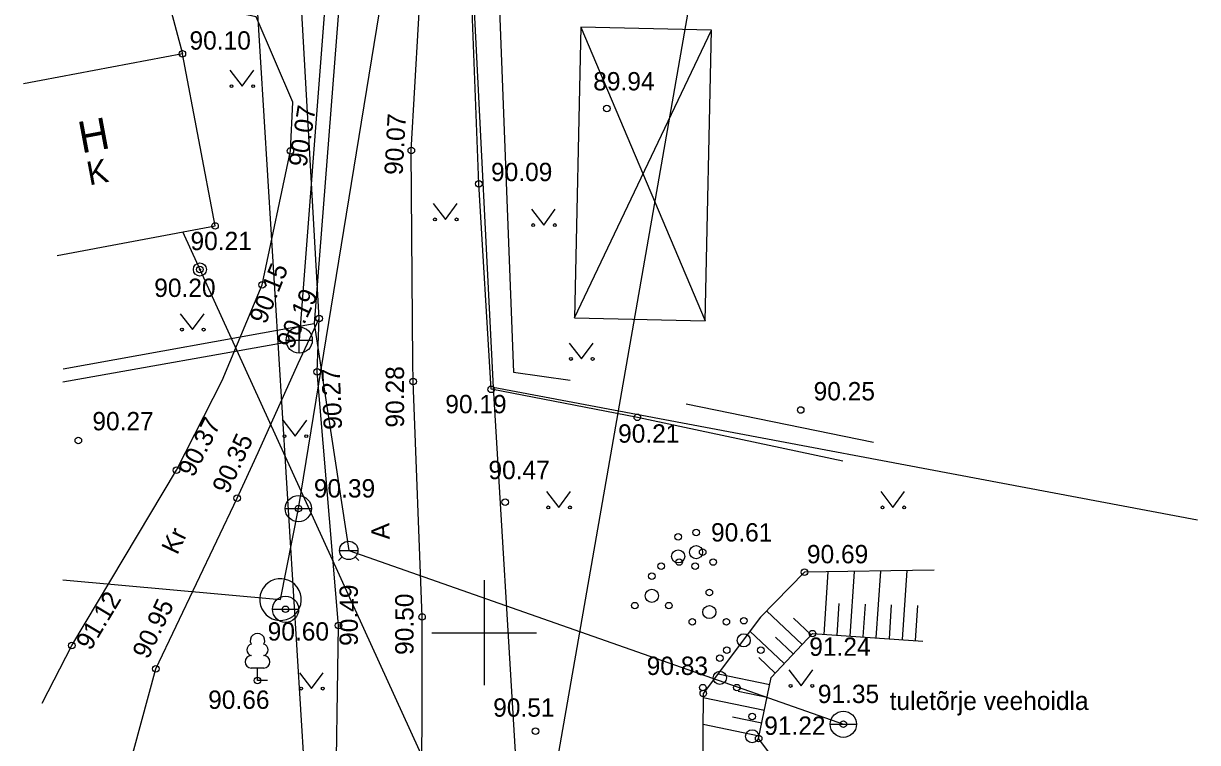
# Model space of a CAD drawing. Extents: x 648748 to 649126, y 6457789 to 6458252.
# Drawn here: x 648932.4 to 648977.24, y 6457945.81 to 6457973.26 of the extents above; entities that cross this region are included whole.
import ezdxf

# ---------------------------------------------------------------- set-up
doc = ezdxf.new("R2010")
doc.units = 0
for name, color, linetype in [('AED', 7, 'Continuous'), ('HALJASTUS', 7, 'Continuous'), ('HOONE', 7, 'Continuous'), ('KKAEV', 7, 'Continuous'), ('KORGUS-EH2000', 7, 'Continuous'), ('KTRASS', 7, 'Continuous'), ('MPOHULIIN', 7, 'Continuous'), ('PIIR', 7, 'Continuous'), ('POST', 7, 'Continuous'), ('PUU', 7, 'Continuous'), ('RAJATIS', 7, 'Continuous'), ('RAJATISEDET', 7, 'Continuous'), ('RELJEEF', 7, 'Continuous'), ('TEE', 7, 'Continuous'), ('VKAEV', 7, 'Continuous'), ('VORK', 7, 'Continuous'), ('VTRASS', 7, 'Continuous')]:
    doc.layers.add(name, color=color, linetype=linetype)

msp = doc.modelspace()

# ---------------------------------------------------------------- linework, layer by layer
at = {"layer": 'AED'}
msp.add_lwpolyline([(648963.692, 6457956.552), (648955.847, 6457958.221), (648950.262, 6457959.291), (648949.792, 6457967.138), (648949.494, 6457974.756), (648949.365, 6457978.667), (648950.63, 6457986.601)], dxfattribs=at)
at = {"layer": 'HALJASTUS'}
for p, q in [((648940.283, 6457971.47), (648940.746, 6457970.863)), ((648940.746, 6457970.863), (648941.192, 6457971.47)), ((648948.052, 6457966.384), (648948.515, 6457965.778)), ((648948.515, 6457965.778), (648948.961, 6457966.384)), ((648951.805, 6457966.17), (648952.269, 6457965.563)), ((648952.269, 6457965.563), (648952.714, 6457966.17)), ((648938.389, 6457962.176), (648938.853, 6457961.57)), ((648938.853, 6457961.57), (648939.298, 6457962.176)), ((648953.249, 6457961.058), (648953.712, 6457960.452)), ((648953.712, 6457960.452), (648954.158, 6457961.058)), ((648942.308, 6457958.108), (648942.772, 6457957.502)), ((648942.772, 6457957.502), (648943.217, 6457958.108)), ((648952.382, 6457955.391), (648952.845, 6457954.784)), ((648952.845, 6457954.784), (648953.291, 6457955.391)), ((648965.147, 6457955.391), (648965.611, 6457954.784)), ((648965.611, 6457954.784), (648966.056, 6457955.391)), ((648942.939, 6457948.473), (648943.403, 6457947.867)), ((648943.403, 6457947.867), (648943.848, 6457948.473)), ((648961.638, 6457948.576), (648962.101, 6457947.969)), ((648962.101, 6457947.969), (648962.547, 6457948.576))]:
    msp.add_line(p, q, dxfattribs=at)
msp.add_lwpolyline([(648951.554, 6457986.197), (648950.426, 6457977.749), (648951.117, 6457959.947)], dxfattribs=at)
for centre in [(648940.345, 6457970.863), (648941.174, 6457970.863), (648948.114, 6457965.778), (648948.943, 6457965.778), (648951.868, 6457965.563), (648952.697, 6457965.563), (648938.452, 6457961.57), (648939.281, 6457961.57), (648953.311, 6457960.452), (648954.14, 6457960.452), (648942.371, 6457957.502), (648943.2, 6457957.502), (648952.444, 6457954.784), (648953.273, 6457954.784), (648965.21, 6457954.784), (648966.039, 6457954.784), (648943.002, 6457947.867), (648943.831, 6457947.867), (648961.7, 6457947.969), (648962.529, 6457947.969)]:
    msp.add_circle(centre, 0.055, dxfattribs=at)
at = {"layer": 'HOONE'}
msp.add_lwpolyline([(648933.683, 6457964.404), (648939.716, 6457965.528), (648938.468, 6457972.096), (648932.399, 6457970.956)], dxfattribs=at)
at = {"layer": 'KKAEV'}
for p, q in [((648942.931, 6457960.671), (648942.931, 6457961.671)), ((648942.431, 6457961.171), (648943.431, 6457961.171))]:
    msp.add_line(p, q, dxfattribs=at)
msp.add_circle((648942.931, 6457961.171), 0.5, dxfattribs=at)
at = {"layer": 'KORGUS-EH2000'}
for centre in [(648938.468, 6457972.096), (648954.679, 6457970.014), (648942.593, 6457968.391), (648947.214, 6457968.405), (648949.792, 6457967.138), (648939.716, 6457965.528), (648939.138, 6457963.865), (648941.516, 6457963.276), (648943.695, 6457961.993), (648943.62, 6457959.958), (648947.283, 6457959.591), (648950.262, 6457959.291), (648962.088, 6457958.501), (648955.847, 6457958.221), (648934.494, 6457957.335), (648938.241, 6457956.206), (648940.562, 6457955.139), (648950.799, 6457954.98), (648942.899, 6457954.736), (648958.342, 6457953.073), (648962.232, 6457952.309), (648942.409, 6457950.893), (648944.43, 6457950.272), (648947.623, 6457950.601), (648962.536, 6457949.964), (648934.246, 6457949.513), (648937.454, 6457948.621), (648941.338, 6457948.175), (648958.367, 6457947.684), (648951.957, 6457946.238), (648963.716, 6457946.505), (648960.481, 6457945.96)]:
    msp.add_circle(centre, 0.125, dxfattribs=at)
at = {"layer": 'KTRASS'}
for p, q in [((648945.475, 6457994.285), (648942.93, 6457961.167)), ((648942.93, 6457961.167), (648933.908, 6457959.562))]:
    msp.add_line(p, q, dxfattribs=at)
at = {"layer": 'MPOHULIIN'}
for points in [[(648951.387, 6457937.05), (648959.585, 6457983.976), (648966.776, 6458026.817), (648933.863, 6458040.57)], [(648951.387, 6457937.05), (648938.48, 6457965.298)]]:
    msp.add_lwpolyline(points, dxfattribs=at)
at = {"layer": 'PIIR'}
for p, q in [((648945.09, 6457912.94), (648941.03, 6457978.89)), ((648949.37, 6457978.67), (648950.34, 6457959.36)), ((648950.34, 6457959.36), (648957.59, 6457839.91)), ((648977.245, 6457954.295), (648950.34, 6457959.36))]:
    msp.add_line(p, q, dxfattribs=at)
at = {"layer": 'POST'}
for radius in [0.25, 0.0234]:
    msp.add_circle((648939.138, 6457963.865), radius, dxfattribs=at)
at = {"layer": 'PUU'}
for p, q in [((648951.117, 6457959.947), (648953.279, 6457959.644)), ((648957.71, 6457958.734), (648964.867, 6457957.27)), ((648941.578, 6457948.65), (648941.098, 6457948.65)), ((648941.338, 6457948.175), (648941.338, 6457948.65)), ((648941.718, 6457948.175), (648941.338, 6457948.175))]:
    msp.add_line(p, q, dxfattribs=at)
for centre, radius in [((648957.408, 6457953.662), 0.125), ((648958.092, 6457953.823), 0.125), ((648957.408, 6457952.912), 0.25), ((648958.092, 6457953.073), 0.25), ((648956.758, 6457952.537), 0.125), ((648957.442, 6457952.698), 0.125), ((648958.058, 6457952.537), 0.125), ((648958.742, 6457952.698), 0.125), ((648956.402, 6457952.159), 0.125), ((648956.402, 6457951.409), 0.25), ((648958.597, 6457951.538), 0.125), ((648955.752, 6457951.034), 0.125), ((648957.052, 6457951.034), 0.125), ((648958.597, 6457950.788), 0.25), ((648957.947, 6457950.413), 0.125), ((648959.247, 6457950.413), 0.125), ((648959.911, 6457950.458), 0.125), ((648959.911, 6457949.708), 0.25), ((648958.999, 6457949.028), 0.125), ((648959.261, 6457949.333), 0.125), ((648960.561, 6457949.333), 0.125), ((648958.999, 6457948.278), 0.25), ((648958.349, 6457947.903), 0.125), ((648959.649, 6457947.903), 0.125), ((648960.233, 6457946.798), 0.125), ((648960.233, 6457946.048), 0.25)]:
    msp.add_circle(centre, radius, dxfattribs=at)
for centre, radius, start, end in [((648941.338, 6457949.695), 0.277, 332.58, 207.42), ((648941.168, 6457949.347), 0.233, 109.022, 253.142), ((648941.508, 6457949.347), 0.233, 286.851, 70.986), ((648941.101, 6457948.887), 0.238, 90.002, 269.395), ((648941.576, 6457948.887), 0.238, 270.605, 89.998)]:
    msp.add_arc(centre, radius, start, end, dxfattribs=at)
at = {"layer": 'RAJATIS'}
msp.add_lwpolyline([(648953.694, 6457973.116), (648953.452, 6457962.018), (648958.442, 6457961.909), (648958.684, 6457973.007), (648953.694, 6457973.116)], dxfattribs=at)
at = {"layer": 'RAJATISEDET'}
for points in [[(648953.452, 6457962.018), (648958.684, 6457973.007)], [(648953.694, 6457973.116), (648958.442, 6457961.909)]]:
    msp.add_lwpolyline(points, dxfattribs=at)
at = {"layer": 'RELJEEF'}
for p, q in [((648963.125, 6457952.323), (648962.966, 6457949.936)), ((648964.129, 6457952.338), (648963.964, 6457949.869)), ((648965.132, 6457952.354), (648964.962, 6457949.802)), ((648966.135, 6457952.37), (648965.959, 6457949.736)), ((648963.546, 6457951.116), (648963.465, 6457949.902)), ((648964.547, 6457951.091), (648964.463, 6457949.836)), ((648965.547, 6457951.065), (648965.461, 6457949.769)), ((648966.548, 6457951.04), (648966.458, 6457949.702)), ((648960.787, 6457950.833), (648962.146, 6457949.55)), ((648961.813, 6457950.552), (648962.489, 6457949.914)), ((648960.15, 6457950.059), (648961.459, 6457948.823)), ((648961.127, 6457949.824), (648961.802, 6457949.187)), ((648960.482, 6457949.058), (648961.116, 6457948.46)), ((648958.929, 6457948.433), (648960.906, 6457948.027)), ((648959.701, 6457947.764), (648960.805, 6457947.537)), ((648958.366, 6457947.528), (648960.705, 6457947.047)), ((648958.358, 6457946.508), (648960.503, 6457946.068)), ((648959.483, 6457946.788), (648960.604, 6457946.557))]:
    msp.add_line(p, q, dxfattribs=at)
for points in [[(648967.183, 6457952.386), (648962.232, 6457952.309), (648960.548, 6457950.589), (648958.367, 6457947.684), (648958.342, 6457944.635), (648961.168, 6457941.363), (648965.243, 6457940.452)], [(648965.793, 6457943.574), (648961.565, 6457944.51), (648960.481, 6457945.96), (648960.961, 6457948.295), (648962.536, 6457949.964), (648966.75, 6457949.683)]]:
    msp.add_lwpolyline(points, dxfattribs=at)
at = {"layer": 'TEE'}
for points in [[(648944.322, 6457942.691), (648944.43, 6457950.272), (648943.62, 6457959.958), (648943.695, 6457961.993), (648942.732, 6457979.09), (648943.931, 6457987.913), (648944.971, 6457991.084), (648946.572, 6457995.932), (648947.397, 6458001.199), (648947.266, 6458002.317), (648949.36, 6458012.048), (648953.85, 6458026.527), (648957.912, 6458044.595), (648958.876, 6458046.069), (648959.537, 6458047.72), (648961.311, 6458058.347), (648962.735, 6458068.115), (648964.651, 6458078.174), (648966.451, 6458083.821)], [(648947.619, 6457941.404), (648947.623, 6457950.601), (648947.283, 6457959.591), (648947.273, 6457960.322), (648947.214, 6457968.405), (648947.766, 6457978.092), (648948.882, 6457987.294), (648949.484, 6457987.338)], [(648933.118, 6457947.307), (648934.246, 6457949.513), (648938.241, 6457956.206), (648939.988, 6457959.622), (648941.516, 6457963.276), (648942.593, 6457968.391), (648942.693, 6457970.259), (648941.285, 6457973.508), (648938.675, 6457974.06), (648937.992, 6457973.906), (648938.468, 6457972.096)], [(648935.36, 6457939.564), (648935.828, 6457943.186), (648936.612, 6457945.525), (648937.454, 6457948.621), (648940.562, 6457955.139), (648941.362, 6457956.879), (648942.888, 6457960.278), (648943.695, 6457961.993)]]:
    msp.add_lwpolyline(points, dxfattribs=at)
at = {"layer": 'VKAEV'}
for p, q in [((648942.399, 6457954.736), (648943.399, 6457954.736)), ((648944.474, 6457953.141), (648945.174, 6457953.141)), ((648944.577, 6457952.894), (648944.437, 6457952.754)), ((648945.072, 6457952.894), (648945.211, 6457952.754)), ((648941.909, 6457950.893), (648942.909, 6457950.893)), ((648963.216, 6457946.505), (648964.216, 6457946.505))]:
    msp.add_line(p, q, dxfattribs=at)
msp.add_lwpolyline([(648943.006, 6457951.351), (648942.979, 6457951.487), (648942.929, 6457951.616), (648942.856, 6457951.734), (648942.765, 6457951.838), (648942.657, 6457951.925), (648942.535, 6457951.991), (648942.404, 6457952.035), (648942.267, 6457952.056), (648942.129, 6457952.053), (648941.993, 6457952.025), (648941.864, 6457951.975), (648941.746, 6457951.903), (648941.642, 6457951.811), (648941.556, 6457951.703), (648941.489, 6457951.581), (648941.445, 6457951.45), (648941.424, 6457951.313), (648941.428, 6457951.175), (648941.455, 6457951.039), (648941.505, 6457950.91), (648941.577, 6457950.792), (648941.669, 6457950.688), (648941.777, 6457950.602), (648941.899, 6457950.535), (648942.03, 6457950.491), (648942.167, 6457950.47), (648942.305, 6457950.474), (648942.441, 6457950.501), (648942.57, 6457950.552), (648942.688, 6457950.624), (648942.792, 6457950.715), (648942.878, 6457950.823), (648942.945, 6457950.945), (648942.989, 6457951.076), (648943.01, 6457951.213), (648943.006, 6457951.351)], dxfattribs=at)
for centre, radius in [((648942.899, 6457954.736), 0.5), ((648944.824, 6457953.141), 0.35), ((648942.409, 6457950.893), 0.5), ((648963.716, 6457946.505), 0.5)]:
    msp.add_circle(centre, radius, dxfattribs=at)
at = {"layer": 'VORK'}
for p, q in [((648950, 6457952), (648950, 6457948)), ((648948, 6457950), (648952, 6457950))]:
    msp.add_line(p, q, dxfattribs=at)
at = {"layer": 'VTRASS'}
for p, q in [((648942.899, 6457954.736), (648954.479, 6458025.55)), ((648942.217, 6457951.263), (648942.899, 6457954.736)), ((648944.824, 6457953.141), (648963.716, 6457946.505)), ((648933.904, 6457952.021), (648942.217, 6457951.263))]:
    msp.add_line(p, q, dxfattribs=at)
for points in [[(648962.127, 6458064.182), (648961.879, 6458062.803), (648959.226, 6458048.095), (648956.066, 6458038.246), (648953.46, 6458026.826), (648953.015, 6458024.876), (648946.034, 6457994.282), (648943.505, 6457961.801)], [(648933.917, 6457960.074), (648943.505, 6457961.801)], [(648943.505, 6457961.801), (648944.824, 6457953.141)]]:
    msp.add_lwpolyline(points, dxfattribs=at)

# ---------------------------------------------------------------- texts
at = {"layer": 'HOONE'}
for s, height, p in [('H', 1.2, (648934.618, 6457968.295)), ('K', 0.9, (648934.911, 6457967.074))]:
    msp.add_text(s, height=height, rotation=10.6387, dxfattribs=at).set_placement(p)
at = {"layer": 'KORGUS-EH2000'}
for s, p in [('90.10', (648938.741, 6457972.259)), ('89.94', (648954.163, 6457970.702)), ('90.09', (648950.258, 6457967.239)), ('90.21', (648938.779, 6457964.604)), ('90.20', (648937.394, 6457962.818)), ('90.25', (648962.581, 6457958.869)), ('90.19', (648948.512, 6457958.377)), ('90.27', (648935.03, 6457957.726)), ('90.21', (648955.112, 6457957.254)), ('90.47', (648950.16, 6457955.861)), ('90.39', (648943.491, 6457955.161)), ('90.61', (648958.662, 6457953.481)), ('90.69', (648962.325, 6457952.65)), ('90.60', (648941.727, 6457949.699)), ('91.24', (648962.415, 6457949.117)), ('90.83', (648956.204, 6457948.386)), ('90.66', (648939.454, 6457947.093)), ('91.35', (648962.741, 6457947.314)), ('90.51', (648950.341, 6457946.793)), ('91.22', (648960.694, 6457946.101))]:
    msp.add_text(s, height=0.7, dxfattribs=at).set_placement(p)
for s, rotation, p in [('90.07', 81.0274, (648943.207, 6457967.755)), ('90.07', 86.7417, (648946.879, 6457967.456)), ('90.15', 68.0304, (648941.649, 6457961.743)), ('90.19', 64.8137, (648942.672, 6457960.791)), ('90.27', 92.1667, (648944.569, 6457957.762)), ('90.28', 90, (648946.935, 6457957.83)), ('90.37', 62.8987, (648938.89, 6457955.898)), ('90.35', 65.3128, (648940.212, 6457955.26)), ('90.49', 90, (648945.171, 6457949.496)), ('91.12', 59.169, (648934.959, 6457949.284)), ('90.95', 64.5062, (648937.157, 6457948.955)), ('90.50', 90, (648947.298, 6457949.152))]:
    msp.add_text(s, height=0.7, rotation=rotation, dxfattribs=at).set_placement(p)
at = {"layer": 'TEE'}
for s, rotation, p in [('Kr', 64.5062, (648938.271, 6457952.942)), ('A', 92.1667, (648946.393, 6457953.568))]:
    msp.add_text(s, height=0.7, rotation=rotation, dxfattribs=at).set_placement(p)
at = {"layer": 'VKAEV'}
msp.add_text('tuletõrje veehoidla', height=0.7, dxfattribs=at).set_placement((648965.486, 6457947.049))

doc.saveas('drawing.dxf')
